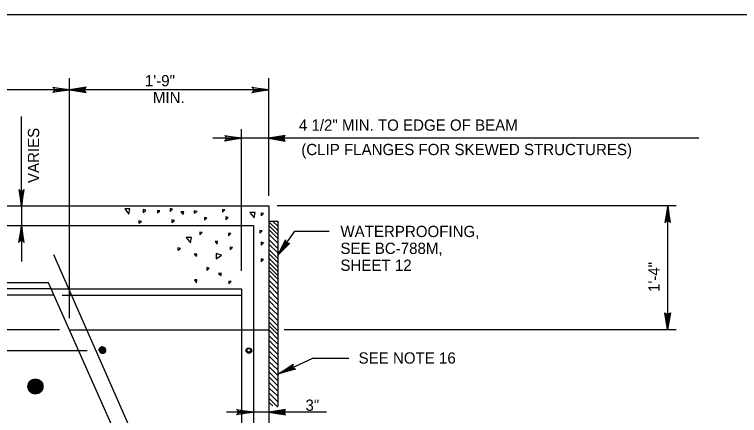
# Model space of a CAD drawing. Extents: x 640009 to 641706, y 298547 to 299735.
# Drawn here: x 640171.1 to 640364.1, y 299019.4 to 299126.2 of the extents above; entities that cross this region are included whole.
import ezdxf

# ---------------------------------------------------------------- set-up
doc = ezdxf.new("R2010")
doc.units = 0
doc.layers.add('1', color=7, linetype='Continuous')

msp = doc.modelspace()

# ---------------------------------------------------------------- linework, layer by layer
at = {"layer": '1'}
for p, q in [((640049.47, 299126.17), (640835.47, 299126.17)), ((640049.47, 299126.17), (640835.47, 299126.17)), ((640185.71, 299045.31), (640185.71, 299109.18)), ((640238.79, 299077.87), (640238.79, 299109.18)), ((640238.79, 299106.08), (640140.79, 299106.08)), ((640172.92, 299075.22), (640172.92, 299098.99)), ((640231.54, 299057.94), (640231.54, 299095.6)), ((640231.54, 299093.22), (640223.92, 299093.22)), ((640353.29, 299093.22), (640231.54, 299093.22)), ((640115.04, 299075.22), (640238.79, 299075.22)), ((640172.92, 299075.22), (640172.92, 299060.35)), ((640223.79, 299075.22), (640230.17, 299075.22)), ((640232.92, 299075.22), (640237.17, 299075.22)), ((640238.79, 299075.22), (640238.79, 298966.97)), ((640347.24, 299075.22), (640241, 299075.22)), ((640344.97, 299042.22), (640344.97, 299075.22)), ((640140.79, 299069.97), (640234.67, 299069.97)), ((640234.67, 299069.97), (640234.67, 299021.1)), ((640238.79, 299071.17), (640241.17, 299071.17)), ((640241.17, 299071.17), (640241.17, 299021.88)), ((640241.17, 299062.02), (640245.71, 299068.44)), ((640245.71, 299068.44), (640254.87, 299068.44)), ((640214.67, 298987.1), (640181.51, 299062.14)), ((640180.17, 299054.72), (640115.04, 299054.72)), ((640219.04, 298966.97), (640180.17, 299054.72)), ((640180.92, 299053.1), (640115.04, 299053.1)), ((640180.92, 299053.1), (640231.54, 299053.1)), ((640231.54, 299053.1), (640231.54, 298966.97)), ((640181.67, 299051.47), (640115.04, 299051.47)), ((640183.79, 299051.47), (640231.54, 299051.47)), ((640183.04, 299042.22), (640128.97, 299042.22)), ((640185.71, 299042.22), (640238.79, 299042.22)), ((640347.24, 299042.22), (640242.86, 299042.22)), ((640190.42, 299036.6), (640158.12, 299036.6)), ((640241.49, 299030.47), (640250.33, 299034.6)), ((640260.04, 299034.6), (640250.33, 299034.6)), ((640254.17, 299020.29), (640227.53, 299020.29)), ((640234.67, 299021.1), (640234.67, 298975.85))]:
    msp.add_line(p, q, dxfattribs=at)
for points in [[(640181.46, 299106.62), (640181.64, 299106.3), (640185.71, 299106.08), (640181.46, 299106.62), (640181.25, 299106.81), (640185.71, 299106.08), (640181.64, 299105.88), (640181.48, 299105.58), (640185.71, 299106.08), (640181.25, 299105.36), (640181.48, 299105.58)], [(640189.95, 299106.62), (640189.78, 299106.3), (640185.71, 299106.08), (640189.95, 299106.62), (640190.16, 299106.81), (640185.71, 299106.08), (640189.78, 299105.88), (640189.93, 299105.58), (640185.71, 299106.08), (640190.16, 299105.36), (640189.93, 299105.58)], [(640234.5, 299106.6), (640234.68, 299106.29), (640238.75, 299106.07), (640234.5, 299106.6), (640234.29, 299106.79), (640238.75, 299106.07), (640234.68, 299105.87), (640234.52, 299105.56), (640238.75, 299106.07), (640234.29, 299105.34), (640234.52, 299105.56)], [(640227.25, 299093.74), (640227.43, 299093.43), (640231.5, 299093.21), (640227.25, 299093.74), (640227.04, 299093.93), (640231.5, 299093.21), (640227.43, 299093.01), (640227.27, 299092.7), (640231.5, 299093.21), (640227.04, 299092.48), (640227.27, 299092.7)], [(640242.96, 299093.74), (640242.78, 299093.43), (640238.71, 299093.21), (640242.96, 299093.74), (640243.17, 299093.93), (640238.71, 299093.21), (640242.78, 299093.01), (640242.94, 299092.7), (640238.71, 299093.21), (640243.17, 299092.48), (640242.94, 299092.7)], [(640172.4, 299079.39), (640172.71, 299079.21), (640172.94, 299075.14), (640172.4, 299079.39), (640172.21, 299079.6), (640172.94, 299075.14), (640173.13, 299079.21), (640173.44, 299079.37), (640172.94, 299075.14), (640173.66, 299079.6), (640173.44, 299079.37)], [(640345.51, 299070.98), (640345.19, 299071.15), (640344.97, 299075.22), (640345.51, 299070.98), (640345.7, 299070.77), (640344.97, 299075.22), (640344.77, 299071.15), (640344.47, 299071), (640344.97, 299075.22), (640344.25, 299070.77), (640344.47, 299071)], [(640173.44, 299065.68), (640173.12, 299065.86), (640172.9, 299069.93), (640173.44, 299065.68), (640173.63, 299065.47), (640172.9, 299069.93), (640172.7, 299065.86), (640172.4, 299065.7), (640172.9, 299069.93), (640172.18, 299065.47), (640172.4, 299065.7)], [(640241.08, 299068.72), (640238.8, 299071)], [(640241.15, 299067.57), (640238.88, 299069.85)], [(640241.15, 299069.8), (640239.78, 299071.17)], [(640241.1, 299066.59), (640238.88, 299068.81)], [(640241.1, 299063.97), (640238.72, 299066.35)], [(640241.13, 299065.36), (640238.79, 299067.7)], [(640244.1, 299065.21), (640243.75, 299065.26), (640241.16, 299062.11), (640244.1, 299065.21), (640244.38, 299065.27), (640241.16, 299062.11), (640243.41, 299065.51), (640243.26, 299065.81), (640241.16, 299062.11), (640243.21, 299066.13), (640243.26, 299065.81)], [(640241.17, 299062.67), (640238.79, 299065.05)], [(640241.13, 299061.26), (640238.79, 299063.59)], [(640241.16, 299060.11), (640238.79, 299062.48)], [(640241.13, 299057.78), (640238.85, 299060.05)], [(640241.2, 299058.85), (640238.92, 299061.13)], [(640241.2, 299056.63), (640238.92, 299058.9)], [(640241.18, 299054.42), (640238.84, 299056.76)], [(640241.14, 299055.65), (640238.92, 299057.87)], [(640241.14, 299053.02), (640238.77, 299055.4)], [(640241.22, 299051.73), (640238.84, 299054.1)], [(640241.22, 299050.27), (640238.84, 299052.65)], [(640241.18, 299048.91), (640238.8, 299051.29)], [(640241.29, 299046.11), (640238.82, 299048.43)], [(640241.29, 299047.46), (640238.85, 299049.9)], [(640241.29, 299044.59), (640238.81, 299047.06)], [(640345.49, 299046.51), (640345.18, 299046.34), (640344.96, 299042.27), (640345.49, 299046.51), (640345.68, 299046.72), (640344.96, 299042.27), (640344.76, 299046.34), (640344.45, 299046.49), (640344.96, 299042.27), (640344.23, 299046.72), (640344.45, 299046.49)], [(640241.29, 299043.21), (640238.81, 299045.69)], [(640241.17, 299040.96), (640238.81, 299043.32)], [(640241.19, 299041.94), (640238.82, 299044.31)], [(640241.29, 299041.84), (640238.91, 299044.22)], [(640241.17, 299038.34), (640238.79, 299040.71)], [(640241.17, 299039.73), (640238.83, 299042.07)], [(640241.17, 299037.07), (640238.79, 299039.45)], [(640193.54, 299036.72), (640194.42, 299037.72)], [(640193.54, 299036.6), (640194.67, 299037.72)], [(640193.54, 299036.72), (640194.54, 299037.72)], [(640193.54, 299036.85), (640194.42, 299037.72)], [(640193.54, 299036.97), (640194.29, 299037.72)], [(640193.67, 299036.47), (640194.79, 299037.72)], [(640193.67, 299036.22), (640195.04, 299037.6)], [(640193.67, 299036.35), (640194.92, 299037.6)], [(640193.67, 299036.47), (640194.79, 299037.6)], [(640193.67, 299037.1), (640194.04, 299037.6)], [(640193.79, 299036.22), (640195.04, 299037.6)], [(640193.79, 299036.1), (640195.17, 299037.47)], [(640193.92, 299036.1), (640195.17, 299037.47)], [(640193.92, 299035.97), (640195.29, 299037.35)], [(640194.04, 299035.97), (640195.29, 299037.35)], [(640194.04, 299035.97), (640195.29, 299037.22)], [(640194.17, 299035.85), (640195.42, 299037.22)], [(640194.17, 299035.85), (640195.42, 299037.1)], [(640194.29, 299035.85), (640195.42, 299037.1)], [(640194.29, 299035.85), (640195.42, 299036.97)], [(640241.17, 299035.62), (640238.79, 299037.99)], [(640194.42, 299035.85), (640195.42, 299036.85)], [(640194.54, 299035.85), (640195.42, 299036.72)], [(640194.67, 299035.85), (640195.42, 299036.6)], [(640194.79, 299035.85), (640195.42, 299036.47)], [(640195.04, 299035.97), (640195.29, 299036.22)], [(640241.17, 299034.26), (640238.79, 299036.64)], [(640241.17, 299032.88), (640238.79, 299035.26)], [(640241.17, 299031.53), (640238.79, 299033.76)], [(640245.62, 299031.79), (640245.33, 299032), (640241.52, 299030.55), (640245.62, 299031.79), (640245.89, 299031.7), (640241.52, 299030.55), (640245.16, 299032.39), (640245.18, 299032.73), (640241.52, 299030.55), (640245.3, 299033.03), (640245.18, 299032.73)], [(640241.17, 299030.01), (640238.79, 299032.39)], [(640241.17, 299028.63), (640238.79, 299031.01)], [(640241.17, 299027.26), (640238.79, 299029.64)], [(640174.79, 299026.56), (640174.68, 299027.19), (640174.9, 299027.92), (640175.58, 299028.69), (640176.22, 299028.96), (640177, 299028.97), (640177.88, 299028.56), (640178.39, 299027.98), (640178.55, 299027.33), (640178.53, 299026.6), (640178.23, 299025.97), (640177.83, 299025.54), (640177.23, 299025.27), (640176.56, 299025.15), (640175.94, 299025.31), (640175.41, 299025.62), (640174.99, 299026.13), (640174.81, 299026.56), (640174.82, 299027.7), (640174.89, 299026.34), (640174.9, 299027.97), (640175.01, 299025.98), (640175.05, 299028.19), (640175.13, 299025.89), (640175.15, 299028.32), (640175.24, 299025.75), (640175.28, 299028.47), (640175.35, 299025.63), (640175.38, 299028.59), (640175.47, 299025.57), (640175.48, 299028.63), (640175.56, 299025.48), (640175.58, 299028.74), (640175.62, 299025.43), (640175.67, 299028.77), (640175.72, 299025.4), (640175.74, 299028.83), (640175.8, 299025.36), (640175.83, 299028.88), (640175.91, 299025.25), (640175.91, 299028.91), (640176.02, 299025.23), (640175.97, 299028.93), (640176.15, 299025.21), (640176.09, 299028.97), (640176.3, 299025.16), (640176.19, 299028.98), (640176.24, 299025.19), (640176.29, 299029.02), (640176.4, 299025.15), (640176.39, 299029.02), (640176.48, 299025.14), (640176.47, 299029.04), (640176.57, 299025.13), (640176.54, 299029.04), (640176.69, 299025.15), (640176.63, 299029.04), (640176.79, 299025.14), (640176.73, 299029.06), (640176.64, 299025.12), (640176.82, 299029.04), (640176.86, 299025.15), (640176.9, 299029.06), (640176.95, 299025.15), (640177, 299029.02), (640177.03, 299025.17), (640177.07, 299028.99), (640177.13, 299025.2), (640177.14, 299028.98), (640177.21, 299025.22), (640177.24, 299028.96), (640177.31, 299025.28), (640177.32, 299028.95), (640177.4, 299025.29), (640177.38, 299028.91), (640177.49, 299025.32), (640177.46, 299028.86), (640177.58, 299025.38), (640177.56, 299028.84), (640177.66, 299025.43), (640177.64, 299028.78), (640177.73, 299025.45), (640177.74, 299028.73), (640177.81, 299025.51), (640177.81, 299028.68), (640177.87, 299025.58), (640177.91, 299028.6), (640177.97, 299025.67), (640178, 299028.49), (640178.08, 299025.76), (640178.1, 299028.37), (640178.21, 299025.89), (640178.18, 299028.28), (640178.33, 299026.14), (640178.29, 299028.2), (640178.29, 299026.07), (640178.36, 299028.07), (640178.39, 299026.22), (640178.44, 299027.9), (640178.45, 299026.35), (640178.51, 299027.7)], [(640178.51, 299027.7), (640178.6, 299027.01), (640177.93, 299025.98), (640176.55, 299025.35), (640174.99, 299026.28), (640174.83, 299027.62), (640176.03, 299028.67), (640177.31, 299028.67), (640178.26, 299028.01), (640178.47, 299026.93), (640177.84, 299025.71), (640178.2, 299026.15), (640176.16, 299025.37), (640175.03, 299026.1), (640174.72, 299027.18), (640175.08, 299027.97), (640175.86, 299028.64), (640176.5, 299028.94), (640177.75, 299028.59)], [(640241.17, 299025.88), (640238.79, 299028.26)], [(640241.17, 299024.53), (640238.79, 299026.76)], [(640241.17, 299023.01), (640238.79, 299025.39)], [(640241.17, 299021.63), (640238.79, 299024.01)], [(640239.82, 299021.97), (640238.85, 299022.87)], [(640230.42, 299020.83), (640230.6, 299020.51), (640234.67, 299020.29), (640230.42, 299020.83), (640230.21, 299021.02), (640234.67, 299020.29), (640230.6, 299020.09), (640230.44, 299019.79), (640234.67, 299020.29), (640230.21, 299019.57), (640230.44, 299019.79)], [(640243.04, 299020.83), (640242.86, 299020.51), (640238.79, 299020.29), (640243.04, 299020.83), (640243.25, 299021.02), (640238.79, 299020.29), (640242.86, 299020.09), (640243.02, 299019.79), (640238.79, 299020.29), (640243.25, 299019.57), (640243.02, 299019.79)]]:
    msp.add_lwpolyline(points, dxfattribs=at)
for points in [[(640200.41, 299074.38), (640201.54, 299073), (640201.79, 299074.38)], [(640205.29, 299073.47), (640206.04, 299074.1), (640205.29, 299074.22)], [(640209.16, 299073.38), (640209.79, 299073.88), (640209.16, 299074)], [(640212.54, 299073.72), (640213.17, 299074.35), (640212.54, 299074.47)], [(640215.38, 299073.62), (640216.01, 299072.87), (640216.13, 299073.62)], [(640218.92, 299073.22), (640219.67, 299073.72), (640218.92, 299073.85)], [(640226.44, 299073.52), (640227.06, 299074.15), (640226.44, 299074.27)], [(640221.7, 299071.37), (640222.32, 299071.99), (640221.7, 299072.12)], [(640227.3, 299071.51), (640227.92, 299072.14), (640227.3, 299072.26)], [(640233.74, 299073.4), (640234.87, 299072.03), (640235.12, 299073.4)], [(640236.78, 299072.52), (640237.4, 299073.14), (640236.78, 299073.27)], [(640204.15, 299070.57), (640204.9, 299071.07), (640204.15, 299071.2)], [(640212.94, 299070.82), (640213.69, 299071.32), (640212.94, 299071.45)], [(640220.41, 299067.49), (640221.03, 299068.12), (640220.41, 299068.24)], [(640228.02, 299067.2), (640228.64, 299067.83), (640228.02, 299067.95)], [(640236.35, 299067.92), (640236.97, 299068.55), (640236.35, 299068.67)], [(640216.78, 299066.74), (640217.91, 299065.37), (640218.16, 299066.74)], [(640214.53, 299063.37), (640215.28, 299063.87), (640214.53, 299063.99)], [(640224.53, 299065.74), (640225.03, 299064.99), (640225.16, 299065.74)], [(640228.45, 299063.47), (640229.07, 299064.09), (640228.45, 299064.22)], [(640236.78, 299064.76), (640237.4, 299065.39), (640236.78, 299065.51)], [(640218.91, 299062.37), (640219.53, 299061.74), (640219.66, 299062.37)], [(640224.78, 299061.12), (640226.16, 299062.12), (640224.78, 299062.49)], [(640236.78, 299060.31), (640237.4, 299060.93), (640236.78, 299061.06)], [(640222.27, 299058.01), (640222.9, 299058.64), (640222.27, 299058.76)], [(640225.41, 299057.24), (640226.03, 299056.62), (640226.16, 299057.24)], [(640219.03, 299055.49), (640219.53, 299054.74), (640219.66, 299055.49)], [(640228.16, 299054.42), (640228.79, 299055.05), (640228.16, 299055.17)]]:
    msp.add_lwpolyline(points, close=True, dxfattribs=at)
for centre, radius in [((640233.38, 299036.7), 0.636), ((640233.49, 299036.64), 0.693), ((640233.44, 299036.76), 0.474), ((640176.65, 299027.09), 2)]:
    msp.add_circle(centre, radius, dxfattribs=at)

# ---------------------------------------------------------------- texts
for s, p in [('1\'-9"', (640205.8, 299107.04)), ('MIN.', (640207.91, 299102.56)), ('4 1/2" MIN. TO EDGE OF BEAM', (640246.79, 299095.22)), ('(CLIP FLANGES FOR SKEWED STRUCTURES)', (640247.42, 299088.72)), ('WATERPROOFING,', (640257.85, 299066.9)), ('SEE BC-788M,', (640257.85, 299062.4)), ('SHEET 12', (640257.85, 299057.9)), ('SEE NOTE 16', (640262.68, 299033.2)), ('3"', (640248.54, 299020.63))]:
    msp.add_text(s, height=3, dxfattribs=at).set_placement(p)
for s, p in [('VARIES', (640177.64, 299081.28)), ('1\'-4"', (640342.83, 299052.28))]:
    msp.add_text(s, height=3, rotation=90, dxfattribs=at).set_placement(p)

doc.saveas('drawing.dxf')
